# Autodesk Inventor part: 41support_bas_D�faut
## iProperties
Created: 2011-01
Part Number: 41support_bas_D�faut
Document SubType Name: Modeling
Designer: eric
Density: 1 g/cm^3
Mass: 167.686 g
Surface Area: 645.645 cm^2
Volume: 167.686 cm^3
Author: eric
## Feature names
1. Base1
